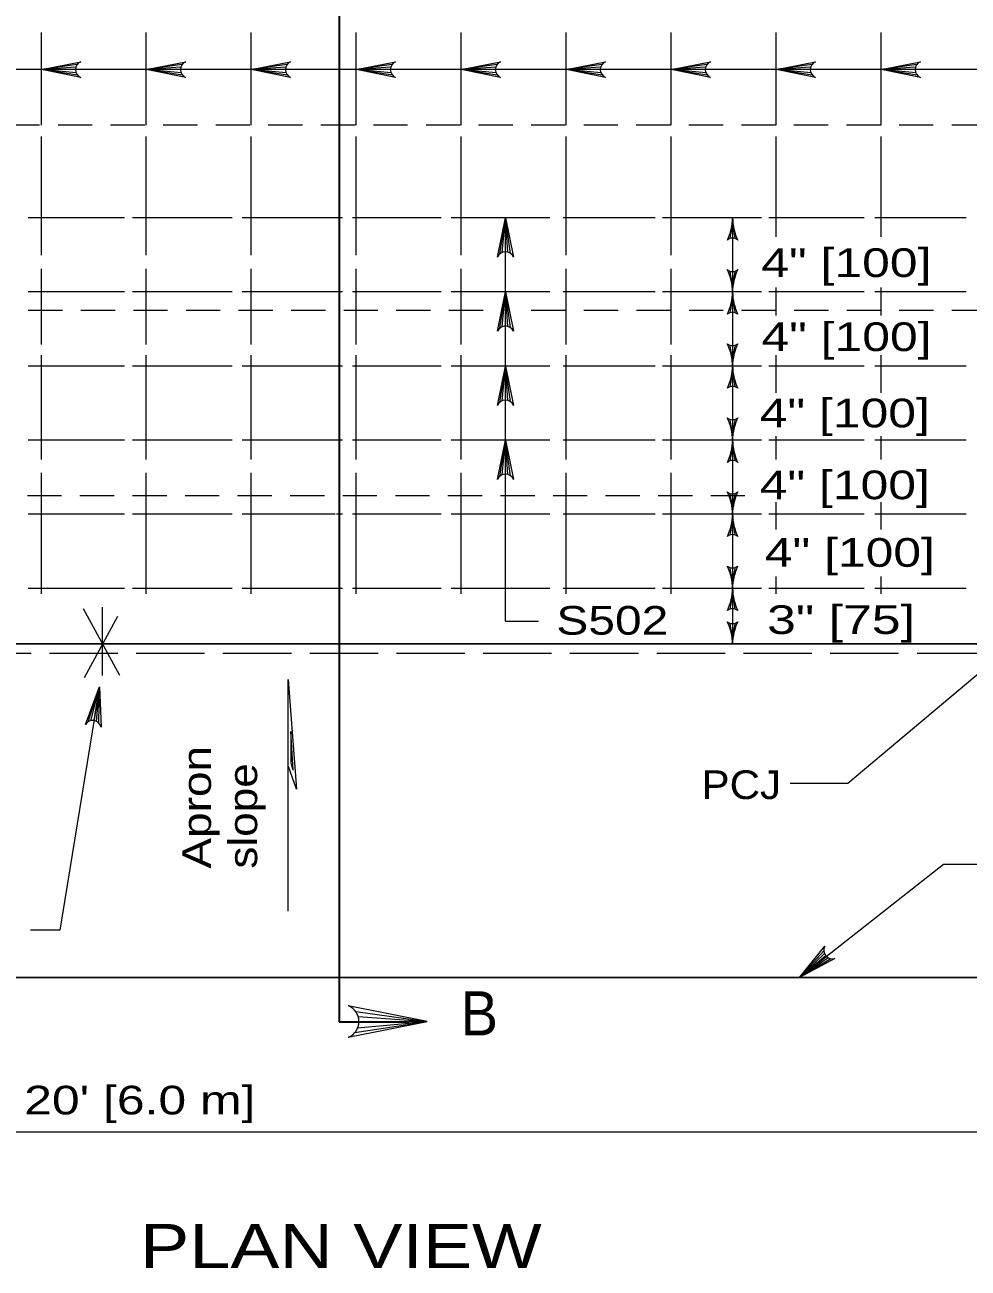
# Model space of a CAD drawing. Extents: x 339.1 to 373.1, y 1412.7 to 1456.7.
# Drawn here: x 351.06 to 356.2, y 1446.17 to 1452.93 of the extents above; entities that cross this region are included whole.
import ezdxf

# ---------------------------------------------------------------- set-up
doc = ezdxf.new("R2010")
doc.units = 0
doc.header["$LTSCALE"] = 0.062
doc.linetypes.add('LONG_DASHED', pattern=[7.5, 6, -1.5])
doc.linetypes.add('MEDIUM_DASHED', pattern=[4.5, 3, -1.5])
doc.layers.add('1', color=7, linetype='Continuous', lineweight=13)

msp = doc.modelspace()

# ---------------------------------------------------------------- linework, layer by layer
at = {"layer": '1', "lineweight": 35}
for p, q in [((352.77492, 1453.91775), (352.77492, 1448.08317)), ((352.77492, 1448.08317), (352.77492, 1447.68517)), ((352.77492, 1447.68517), (352.77492, 1447.50858)), ((352.77492, 1447.50858), (353.15442, 1447.50858))]:
    msp.add_line(p, q, dxfattribs=at)
at = {"layer": '1'}
for p, q in [((351.15408, 1452.38633), (351.15408, 1452.89025)), ((351.72525, 1452.38633), (351.72525, 1452.89025)), ((352.29633, 1452.38633), (352.29633, 1452.89025)), ((352.86742, 1452.38633), (352.86742, 1452.89025)), ((353.43858, 1452.38633), (353.43858, 1452.89025)), ((354.00967, 1452.38633), (354.00967, 1452.89025)), ((354.58083, 1452.38633), (354.58083, 1452.89025)), ((355.15192, 1452.38633), (355.15192, 1452.89025)), ((355.72308, 1452.38633), (355.72308, 1452.89025)), ((351.348, 1452.71575), (351.15408, 1452.68867)), ((351.34142, 1452.70233), (351.15408, 1452.68867)), ((351.91908, 1452.71575), (351.72525, 1452.68867)), ((351.9125, 1452.70233), (351.72525, 1452.68867)), ((352.49025, 1452.71575), (352.29633, 1452.68867)), ((352.48367, 1452.70233), (352.29633, 1452.68867)), ((353.06133, 1452.71575), (352.86742, 1452.68867)), ((353.05475, 1452.70233), (352.86742, 1452.68867)), ((353.6325, 1452.71575), (353.43858, 1452.68867)), ((353.62592, 1452.70233), (353.43858, 1452.68867)), ((354.20358, 1452.71575), (354.00967, 1452.68867)), ((354.197, 1452.70233), (354.00967, 1452.68867)), ((354.77475, 1452.71575), (354.58083, 1452.68867)), ((354.76817, 1452.70233), (354.58083, 1452.68867)), ((355.34583, 1452.71575), (355.15192, 1452.68867)), ((355.33925, 1452.70233), (355.15192, 1452.68867)), ((355.91692, 1452.71575), (355.72308, 1452.68867)), ((355.91042, 1452.70233), (355.72308, 1452.68867)), ((351.33942, 1452.68867), (351.15408, 1452.68867)), ((351.34283, 1452.67125), (351.15408, 1452.68867)), ((351.35025, 1452.65867), (351.15408, 1452.68867)), ((351.91058, 1452.68867), (351.72525, 1452.68867)), ((351.914, 1452.67125), (351.72525, 1452.68867)), ((351.92142, 1452.65867), (351.72525, 1452.68867)), ((352.48167, 1452.68867), (352.29633, 1452.68867)), ((352.48508, 1452.67125), (352.29633, 1452.68867)), ((352.4925, 1452.65867), (352.29633, 1452.68867)), ((353.05275, 1452.68867), (352.86742, 1452.68867)), ((353.05625, 1452.67125), (352.86742, 1452.68867)), ((353.06367, 1452.65867), (352.86742, 1452.68867)), ((353.62392, 1452.68867), (353.43858, 1452.68867)), ((353.62733, 1452.67125), (353.43858, 1452.68867)), ((353.63475, 1452.65867), (353.43858, 1452.68867)), ((354.58083, 1452.68867), (354.00967, 1452.68867)), ((354.195, 1452.68867), (354.00967, 1452.68867)), ((354.19842, 1452.67125), (354.00967, 1452.68867)), ((354.20592, 1452.65867), (354.00967, 1452.68867)), ((354.76617, 1452.68867), (354.58083, 1452.68867)), ((354.76958, 1452.67125), (354.58083, 1452.68867)), ((354.777, 1452.65867), (354.58083, 1452.68867)), ((355.33725, 1452.68867), (355.15192, 1452.68867)), ((355.34067, 1452.67125), (355.15192, 1452.68867)), ((355.34808, 1452.65867), (355.15192, 1452.68867)), ((355.90842, 1452.68867), (355.72308, 1452.68867)), ((355.91183, 1452.67125), (355.72308, 1452.68867)), ((355.91925, 1452.65867), (355.72308, 1452.68867)), ((351.15408, 1451.67858), (351.15408, 1452.32525)), ((351.72525, 1451.67858), (351.72525, 1452.32525)), ((352.29633, 1451.67858), (352.29633, 1452.32525)), ((352.86742, 1451.67858), (352.86742, 1452.32525)), ((353.43858, 1451.67858), (353.43858, 1452.32525)), ((354.00967, 1451.67858), (354.00967, 1452.32525)), ((354.58083, 1451.67858), (354.58083, 1452.32525)), ((355.15192, 1451.77942), (355.15192, 1452.32525)), ((355.72308, 1451.77942), (355.72308, 1452.32525)), ((351.60583, 1451.88242), (351.082, 1451.88242)), ((352.1925, 1451.88242), (351.65067, 1451.88242)), ((352.79242, 1451.88242), (352.24617, 1451.88242)), ((353.32967, 1451.88242), (352.84617, 1451.88242)), ((353.92067, 1451.88242), (353.3835, 1451.88242)), ((353.64925, 1451.68667), (353.67917, 1451.88283)), ((353.66175, 1451.69408), (353.67917, 1451.88283)), ((353.67917, 1451.47933), (353.67917, 1451.88283)), ((353.67917, 1451.6975), (353.67917, 1451.88283)), ((353.69292, 1451.6955), (353.67917, 1451.88283)), ((353.70633, 1451.689), (353.67917, 1451.88283)), ((354.49392, 1451.88242), (353.99233, 1451.88242)), ((355.0715, 1451.88242), (354.53425, 1451.88242)), ((355.63117, 1451.88242), (355.11183, 1451.88242)), ((356.18633, 1451.88242), (355.68933, 1451.88242)), ((351.15408, 1451.19358), (351.15408, 1451.6055)), ((351.72525, 1451.19358), (351.72525, 1451.6055)), ((352.29633, 1451.19358), (352.29633, 1451.6055)), ((352.86742, 1451.19358), (352.86742, 1451.6055)), ((353.43858, 1451.19358), (353.43858, 1451.6055)), ((354.00967, 1451.19358), (354.00967, 1451.6055)), ((354.58083, 1451.19358), (354.58083, 1451.6055)), ((355.15192, 1451.35067), (355.15192, 1451.50408)), ((355.72308, 1451.35067), (355.72308, 1451.50408)), ((351.60583, 1451.47933), (351.082, 1451.47933)), ((352.1925, 1451.47933), (351.65067, 1451.47933)), ((352.79242, 1451.47933), (352.24617, 1451.47933)), ((353.32967, 1451.47933), (352.84617, 1451.47933)), ((353.92067, 1451.47933), (353.3835, 1451.47933)), ((353.64925, 1451.28317), (353.67917, 1451.47933)), ((353.66175, 1451.29058), (353.67917, 1451.47933)), ((353.67917, 1451.07625), (353.67917, 1451.47933)), ((353.67917, 1451.294), (353.67917, 1451.47933)), ((353.69292, 1451.292), (353.67917, 1451.47933)), ((353.70633, 1451.2855), (353.67917, 1451.47933)), ((354.49392, 1451.47933), (353.99233, 1451.47933)), ((355.0715, 1451.47933), (354.53425, 1451.47933)), ((355.63117, 1451.47933), (355.11183, 1451.47933)), ((356.18633, 1451.47933), (355.68933, 1451.47933)), ((351.15408, 1450.56767), (351.15408, 1451.13608)), ((351.72525, 1450.56767), (351.72525, 1451.13608)), ((352.29633, 1450.56767), (352.29633, 1451.13608)), ((352.86742, 1450.56767), (352.86742, 1451.13608)), ((353.43858, 1450.56767), (353.43858, 1451.13608)), ((354.00967, 1450.56767), (354.00967, 1451.13608)), ((354.58083, 1450.56767), (354.58083, 1451.13608)), ((355.15192, 1450.92983), (355.15192, 1451.13608)), ((355.72308, 1450.92983), (355.72308, 1451.13608)), ((351.60583, 1451.07625), (351.082, 1451.07625)), ((352.1925, 1451.07625), (351.65067, 1451.07625)), ((352.79242, 1451.07625), (352.24617, 1451.07625)), ((353.32967, 1451.07625), (352.84617, 1451.07625)), ((353.92067, 1451.07625), (353.3835, 1451.07625)), ((353.64925, 1450.88008), (353.67917, 1451.07625)), ((353.66175, 1450.8875), (353.67917, 1451.07625)), ((353.67917, 1450.89092), (353.67917, 1451.07625)), ((353.69292, 1450.88892), (353.67917, 1451.07625)), ((353.70633, 1450.88233), (353.67917, 1451.07625)), ((354.49392, 1451.07625), (353.99233, 1451.07625)), ((355.0715, 1451.07625), (354.53425, 1451.07625)), ((355.63117, 1451.07625), (355.11183, 1451.07625)), ((356.18633, 1451.07625), (355.68933, 1451.07625)), ((355.15192, 1450.56767), (355.15192, 1450.69383)), ((355.72308, 1450.56767), (355.72308, 1450.69383)), ((351.60583, 1450.67317), (351.082, 1450.67317)), ((352.1925, 1450.67317), (351.65067, 1450.67317)), ((352.79242, 1450.67317), (352.24617, 1450.67317)), ((353.32967, 1450.67317), (352.84617, 1450.67317)), ((353.92067, 1450.67317), (353.3835, 1450.67317)), ((353.64925, 1450.477), (353.67917, 1450.67317)), ((353.66175, 1450.48442), (353.67917, 1450.67317)), ((353.67917, 1450.48783), (353.67917, 1450.67317)), ((353.69292, 1450.48583), (353.67917, 1450.67317)), ((353.70633, 1450.47925), (353.67917, 1450.67317)), ((354.49392, 1450.67317), (353.99233, 1450.67317)), ((355.0715, 1450.67317), (354.53425, 1450.67317)), ((355.63117, 1450.67317), (355.11183, 1450.67317)), ((356.18633, 1450.67317), (355.68933, 1450.67317)), ((351.15408, 1449.8375), (351.15408, 1450.49467)), ((351.72525, 1449.8375), (351.72525, 1450.49467)), ((352.29633, 1449.8375), (352.29633, 1450.49467)), ((352.86742, 1449.8375), (352.86742, 1450.49467)), ((353.43858, 1449.8375), (353.43858, 1450.49467)), ((354.00967, 1449.8375), (354.00967, 1450.49467)), ((354.58083, 1449.8375), (354.58083, 1450.49467)), ((355.15192, 1450.18642), (355.15192, 1450.33592)), ((355.72308, 1450.18642), (355.72308, 1450.33592)), ((351.60583, 1450.27008), (351.082, 1450.27008)), ((352.1925, 1450.27008), (351.65067, 1450.27008)), ((352.75325, 1450.27008), (352.24617, 1450.27008)), ((352.79242, 1450.27008), (352.76, 1450.27008)), ((353.32967, 1450.27008), (352.84617, 1450.27008)), ((353.92067, 1450.27008), (353.3835, 1450.27008)), ((354.49392, 1450.27008), (353.99233, 1450.27008)), ((355.0715, 1450.27008), (354.53425, 1450.27008)), ((355.63117, 1450.27008), (355.11183, 1450.27008)), ((356.18633, 1450.27008), (355.68933, 1450.27008)), ((355.15192, 1449.8375), (355.15192, 1449.93075)), ((355.72308, 1449.8375), (355.72308, 1449.93075)), ((351.60583, 1449.86692), (351.082, 1449.86692)), ((352.1925, 1449.86692), (351.65067, 1449.86692)), ((352.79242, 1449.86692), (352.24617, 1449.86692)), ((353.32967, 1449.86692), (352.84617, 1449.86692)), ((353.92067, 1449.86692), (353.3835, 1449.86692)), ((354.49392, 1449.86692), (353.99233, 1449.86692)), ((355.0715, 1449.86692), (354.53425, 1449.86692)), ((355.63117, 1449.86692), (355.11183, 1449.86692)), ((356.18633, 1449.86692), (355.68933, 1449.86692)), ((351.581, 1449.39258), (351.383, 1449.75583)), ((351.48725, 1449.39358), (351.48725, 1449.76375)), ((351.38808, 1449.38275), (351.57008, 1449.7165)), ((353.67917, 1449.68867), (353.85825, 1449.68867)), ((351.4705, 1449.33042), (351.25492, 1448.0085)), ((351.40975, 1449.1415), (351.4705, 1449.33042)), ((351.42333, 1449.14683), (351.4705, 1449.33042)), ((351.44117, 1449.1475), (351.4705, 1449.33042)), ((351.45433, 1449.14333), (351.4705, 1449.33042)), ((351.4665, 1449.13475), (351.4705, 1449.33042)), ((355.41125, 1447.89492), (355.27908, 1447.7505)), ((355.41475, 1447.88042), (355.27908, 1447.7505)), ((355.42192, 1447.86858), (355.27908, 1447.7505)), ((355.43567, 1447.85733), (355.27908, 1447.7505)), ((355.44942, 1447.85242), (355.27908, 1447.7505)), ((352.86467, 1447.565), (353.2525, 1447.51075)), ((352.86008, 1447.45083), (353.2525, 1447.51075)), ((352.87492, 1447.47592), (353.2525, 1447.51075)), ((352.87783, 1447.53817), (353.2525, 1447.51075)), ((352.88183, 1447.51075), (353.2525, 1447.51075))]:
    msp.add_line(p, q, dxfattribs=at)
at = {"layer": '1', "linetype": 'MEDIUM_DASHED'}
for p, q in [((357.15083, 1452.38633), (345.68083, 1452.38633)), ((353.55717, 1451.37858), (348.86958, 1451.37858)), ((356.57975, 1451.37858), (353.80425, 1451.37858)), ((354.98208, 1450.37083), (345.82367, 1450.37083))]:
    msp.add_line(p, q, dxfattribs=at)
at = {"layer": '1', "lineweight": 25}
for p, q in [((360.97275, 1449.56467), (343.61608, 1449.56467)), ((353.90383, 1447.75067), (348.158, 1447.75067)), ((358.86425, 1447.75067), (353.90383, 1447.75067))]:
    msp.add_line(p, q, dxfattribs=at)
at = {"layer": '1', "linetype": 'LONG_DASHED'}
msp.add_line((345.06217, 1449.51425), (357.91233, 1449.51425), dxfattribs=at)
at = {"layer": '1'}
for points in [[(351.36825, 1452.64583), (351.15408, 1452.68867), (351.36825, 1452.7315)], [(351.93942, 1452.64583), (351.72525, 1452.68867), (351.93942, 1452.7315)], [(352.5105, 1452.64583), (352.29633, 1452.68867), (352.5105, 1452.7315)], [(353.08167, 1452.64583), (352.86742, 1452.68867), (353.08167, 1452.7315)], [(353.65275, 1452.64583), (353.43858, 1452.68867), (353.65275, 1452.7315)], [(354.22383, 1452.64583), (354.00967, 1452.68867), (354.22383, 1452.7315)], [(354.795, 1452.64583), (354.58083, 1452.68867), (354.795, 1452.7315)], [(355.36608, 1452.64583), (355.15192, 1452.68867), (355.36608, 1452.7315)], [(355.93725, 1452.64583), (355.72308, 1452.68867), (355.93725, 1452.7315)], [(354.00967, 1452.68867), (353.43858, 1452.68867), (352.86742, 1452.68867), (352.29633, 1452.68867), (351.72525, 1452.68867), (351.15408, 1452.68867), (350.583, 1452.68867), (350.01183, 1452.68867)], [(355.72308, 1452.68867), (355.15192, 1452.68867), (354.58083, 1452.68867)], [(357.219, 1452.68867), (356.86533, 1452.68867), (356.29417, 1452.68867), (355.72308, 1452.68867)], [(353.63633, 1451.66867), (353.67917, 1451.88283), (353.722, 1451.66867)], [(354.91467, 1451.88242), (354.91467, 1451.47933), (354.91467, 1451.07625), (354.91467, 1450.67317), (354.91467, 1450.27008), (354.91467, 1449.86692), (354.91467, 1449.56467)], [(353.63633, 1451.26517), (353.67917, 1451.47933), (353.722, 1451.26517)], [(353.63633, 1450.86208), (353.67917, 1451.07625), (353.722, 1450.86208)], [(353.67917, 1449.68867), (353.67917, 1450.67317), (353.67917, 1451.07625)], [(353.63633, 1450.459), (353.67917, 1450.67317), (353.722, 1450.459)], [(357.15083, 1450.157), (355.54258, 1448.80458), (355.22842, 1448.80458)], [(351.39425, 1449.12567), (351.4705, 1449.33042), (351.47883, 1449.11217)], [(352.497, 1448.11142), (352.497, 1449.37183), (352.5425, 1448.77408), (352.49892, 1448.89842)], [(352.5235, 1448.8785), (352.51217, 1449.08742), (352.51217, 1448.91808), (352.51967, 1448.88217)], [(355.27908, 1447.7505), (356.0625, 1448.36683), (356.33358, 1448.36683)], [(351.25492, 1448.0085), (351.25492, 1448.0085), (351.09567, 1448.0085)], [(355.47142, 1447.85392), (355.27908, 1447.7505), (355.41683, 1447.92)], [(352.82408, 1447.42508), (353.2525, 1447.51075), (352.82408, 1447.59642)], [(357.15083, 1446.90983), (352.38625, 1446.90983), (345.82367, 1446.90983)]]:
    msp.add_lwpolyline(points, dxfattribs=at)
for centre, radius, start, end in [((351.38556, 1452.68871), 0.04623, 112.08782, 247.91395), ((351.95668, 1452.68871), 0.04623, 112.08782, 247.91395), ((352.5278, 1452.68871), 0.04623, 112.08782, 247.91395), ((353.09892, 1452.68871), 0.04623, 112.08782, 247.91395), ((353.67004, 1452.68871), 0.04623, 112.08782, 247.91395), ((354.24116, 1452.68871), 0.04623, 112.08782, 247.91395), ((354.81228, 1452.68871), 0.04623, 112.08782, 247.91395), ((355.3834, 1452.68871), 0.04623, 112.08782, 247.91395), ((355.95452, 1452.68871), 0.04623, 112.08782, 247.91395), ((353.67925, 1451.65139), 0.04623, 22.08782, 157.91395), ((353.67925, 1451.24789), 0.04623, 22.08782, 157.91395), ((353.67925, 1450.84479), 0.04623, 22.08782, 157.91395), ((353.67925, 1450.44169), 0.04623, 22.08782, 157.91395), ((351.43388, 1449.1019), 0.04623, 12.96379, 148.78991), ((355.45745, 1447.89801), 0.04623, 151.66525, 287.49138), ((352.78953, 1447.51087), 0.09245, 292.08605, 67.91218)]:
    msp.add_arc(centre, radius, start, end, dxfattribs=at)
for centre, major_axis, ratio, start_param, end_param in [((354.66134, 1451.88519), (0, -0.26833), 0.944544, 1.0914021, 1.5602334), ((354.7881, 1451.88509), (0.00517, 0.26826), 0.472393, 4.2754323, 4.7112945), ((355.16341, 1451.88414), (0, -0.26334), 0.944544, 4.718777, 5.1971336), ((355.04154, 1451.88509), (-0.00517, 0.26826), 0.472393, 1.5696307, 2.0080981), ((354.91477, 1451.72162), (0, 0.04999), 0.944544, 5.6336903, 6.9326805), ((354.66594, 1451.47768), (0, 0.26334), 0.944544, 4.718777, 5.1971336), ((354.91458, 1451.6402), (0, -0.04999), 0.944544, 5.6336903, 6.9326805), ((354.78782, 1451.47673), (-0.00517, 0.26826), 0.472393, 4.7112233, 5.1496908), ((355.04125, 1451.47673), (0.00517, 0.26826), 0.472393, 1.1338397, 1.5697019), ((355.16802, 1451.47663), (0, 0.26833), 0.944544, 1.0914021, 1.5602334), ((354.66134, 1451.48209), (0, -0.26833), 0.944544, 1.0914021, 1.5602334), ((354.7881, 1451.48199), (0.00517, 0.26826), 0.472393, 4.2754323, 4.7112945), ((355.16341, 1451.48104), (0, -0.26334), 0.944544, 4.718777, 5.1971336), ((355.04154, 1451.48199), (-0.00517, 0.26826), 0.472393, 1.5696307, 2.0080981), ((354.91477, 1451.31852), (0, 0.04999), 0.944544, 5.6336903, 6.9326805), ((354.66594, 1451.07458), (0, 0.26334), 0.944544, 4.718777, 5.1971336), ((354.91458, 1451.2371), (0, -0.04999), 0.944544, 5.6336903, 6.9326805), ((354.78782, 1451.07362), (-0.00517, 0.26826), 0.472393, 4.7112233, 5.1496908), ((355.04125, 1451.07362), (0.00517, 0.26826), 0.472393, 1.1338397, 1.5697019), ((355.16802, 1451.07352), (0, 0.26833), 0.944544, 1.0914021, 1.5602334), ((354.66134, 1451.07899), (0, -0.26833), 0.944544, 1.0914021, 1.5602334), ((354.7881, 1451.07889), (0.00517, 0.26826), 0.472393, 4.2754323, 4.7112945), ((355.16341, 1451.07794), (0, -0.26334), 0.944544, 4.718777, 5.1971336), ((355.04154, 1451.07889), (-0.00517, 0.26826), 0.472393, 1.5696307, 2.0080981), ((354.91477, 1450.91542), (0, 0.04999), 0.944544, 5.6336903, 6.9326805), ((354.91458, 1450.834), (0, -0.04999), 0.944544, 5.6336903, 6.9326805), ((354.66594, 1450.67147), (0, 0.26334), 0.944544, 4.718777, 5.1971336), ((354.78782, 1450.67052), (-0.00517, 0.26826), 0.472393, 4.7112233, 5.1496908), ((355.04125, 1450.67052), (0.00517, 0.26826), 0.472393, 1.1338397, 1.5697019), ((355.16802, 1450.67042), (0, 0.26833), 0.944544, 1.0914021, 1.5602334), ((355.04154, 1450.67579), (-0.00517, 0.26826), 0.472393, 1.5696307, 2.0080981), ((354.66134, 1450.67589), (0, -0.26833), 0.944544, 1.0914021, 1.5602334), ((354.7881, 1450.67579), (0.00517, 0.26826), 0.472393, 4.2754323, 4.7112945), ((355.16341, 1450.67484), (0, -0.26334), 0.944544, 4.718777, 5.1971336), ((354.91477, 1450.51231), (0, 0.04999), 0.944544, 5.6336903, 6.9326805), ((354.91458, 1450.4309), (0, -0.04999), 0.944544, 5.6336903, 6.9326805), ((354.66594, 1450.26837), (0, 0.26334), 0.944544, 4.718777, 5.1971336), ((354.78782, 1450.26742), (-0.00517, 0.26826), 0.472393, 4.7112233, 5.1496908), ((355.04125, 1450.26742), (0.00517, 0.26826), 0.472393, 1.1338397, 1.5697019), ((355.16802, 1450.26732), (0, 0.26833), 0.944544, 1.0914021, 1.5602334), ((354.66134, 1450.27279), (0, -0.26833), 0.944544, 1.0914021, 1.5602334), ((354.7881, 1450.27269), (0.00517, 0.26826), 0.472393, 4.2754323, 4.7112945), ((355.16341, 1450.27174), (0, -0.26334), 0.944544, 4.718777, 5.1971336), ((355.04154, 1450.27269), (-0.00517, 0.26826), 0.472393, 1.5696307, 2.0080981), ((354.91477, 1450.10921), (0, 0.04999), 0.944544, 5.6336903, 6.9326805), ((354.91458, 1450.0278), (0, -0.04999), 0.944544, 5.6336903, 6.9326805), ((354.66594, 1449.86527), (0, 0.26334), 0.944544, 4.718777, 5.1971336), ((354.78782, 1449.86432), (-0.00517, 0.26826), 0.472393, 4.7112233, 5.1496908), ((355.04125, 1449.86432), (0.00517, 0.26826), 0.472393, 1.1338397, 1.5697019), ((355.16802, 1449.86422), (0, 0.26833), 0.944544, 1.0914021, 1.5602334), ((354.66134, 1449.86969), (0, -0.26833), 0.944544, 1.0914021, 1.5602334), ((354.7881, 1449.86959), (0.00517, 0.26826), 0.472393, 4.2754323, 4.7112945), ((355.16341, 1449.86864), (0, -0.26334), 0.944544, 4.718777, 5.1971336), ((355.04154, 1449.86959), (-0.00517, 0.26826), 0.472393, 1.5696307, 2.0080981), ((354.91477, 1449.70611), (0, 0.04999), 0.944544, 5.6336903, 6.9326805), ((354.66594, 1449.56295), (0, 0.26334), 0.944544, 4.718777, 5.1971336), ((354.91458, 1449.72547), (0, -0.04999), 0.944544, 5.6336903, 6.9326805), ((354.78782, 1449.562), (-0.00517, 0.26826), 0.472393, 4.7112233, 5.1496908), ((355.04125, 1449.562), (0.00517, 0.26826), 0.472393, 1.1338397, 1.5697019), ((355.16802, 1449.56189), (0, 0.26833), 0.944544, 1.0914021, 1.5602334)]:
    msp.add_ellipse(centre, major_axis=major_axis, ratio=ratio, start_param=start_param, end_param=end_param, dxfattribs=at)

# ---------------------------------------------------------------- texts
for s, height, width, p in [('4" [100]', 0.156, 1.3, (355.07083, 1451.56042)), ('4" [100]', 0.156, 1.3, (355.07167, 1451.1575)), ('4" [100]', 0.156, 1.3, (355.06233, 1450.74267)), ('4" [100]', 0.156, 1.3, (355.06233, 1450.35158)), ('4" [100]', 0.156, 1.3, (355.08992, 1449.98417)), ('S502', 0.156, 1.25, (353.956, 1449.61492)), ('3" [75]', 0.156, 1.35, (355.10233, 1449.61875)), ('PCJ', 0.156, 1.1, (354.74542, 1448.72083)), ('B', 0.24, 0.95, (353.43533, 1447.43525)), ("Variable 6' [1.8 m] to 20' [6.0 m]", 0.156, 1.3, (348.50683, 1447.00542)), ('PLAN VIEW', 0.24, 1.25, (351.69142, 1446.16942))]:
    msp.add_text(s, height=height, dxfattribs=dict(at, width=width)).set_placement(p)
for s, width, p in [('Apron', 1.2, (352.07708, 1448.34225)), ('slope', 1.15, (352.32825, 1448.34225))]:
    msp.add_text(s, height=0.156, rotation=90, dxfattribs=dict(at, width=width)).set_placement(p)

doc.saveas('drawing.dxf')
